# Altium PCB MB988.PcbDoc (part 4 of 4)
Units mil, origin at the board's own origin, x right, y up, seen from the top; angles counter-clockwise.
Board outline 4505 x 6805 mil, 4 copper layers (TopLayer, VCC, GND, BottomLayer), stack 71.6 mil thick; 546 components, 390 nets, 1907 pads, 809 vias.
Unrouted connection lines stored in the file: 2.
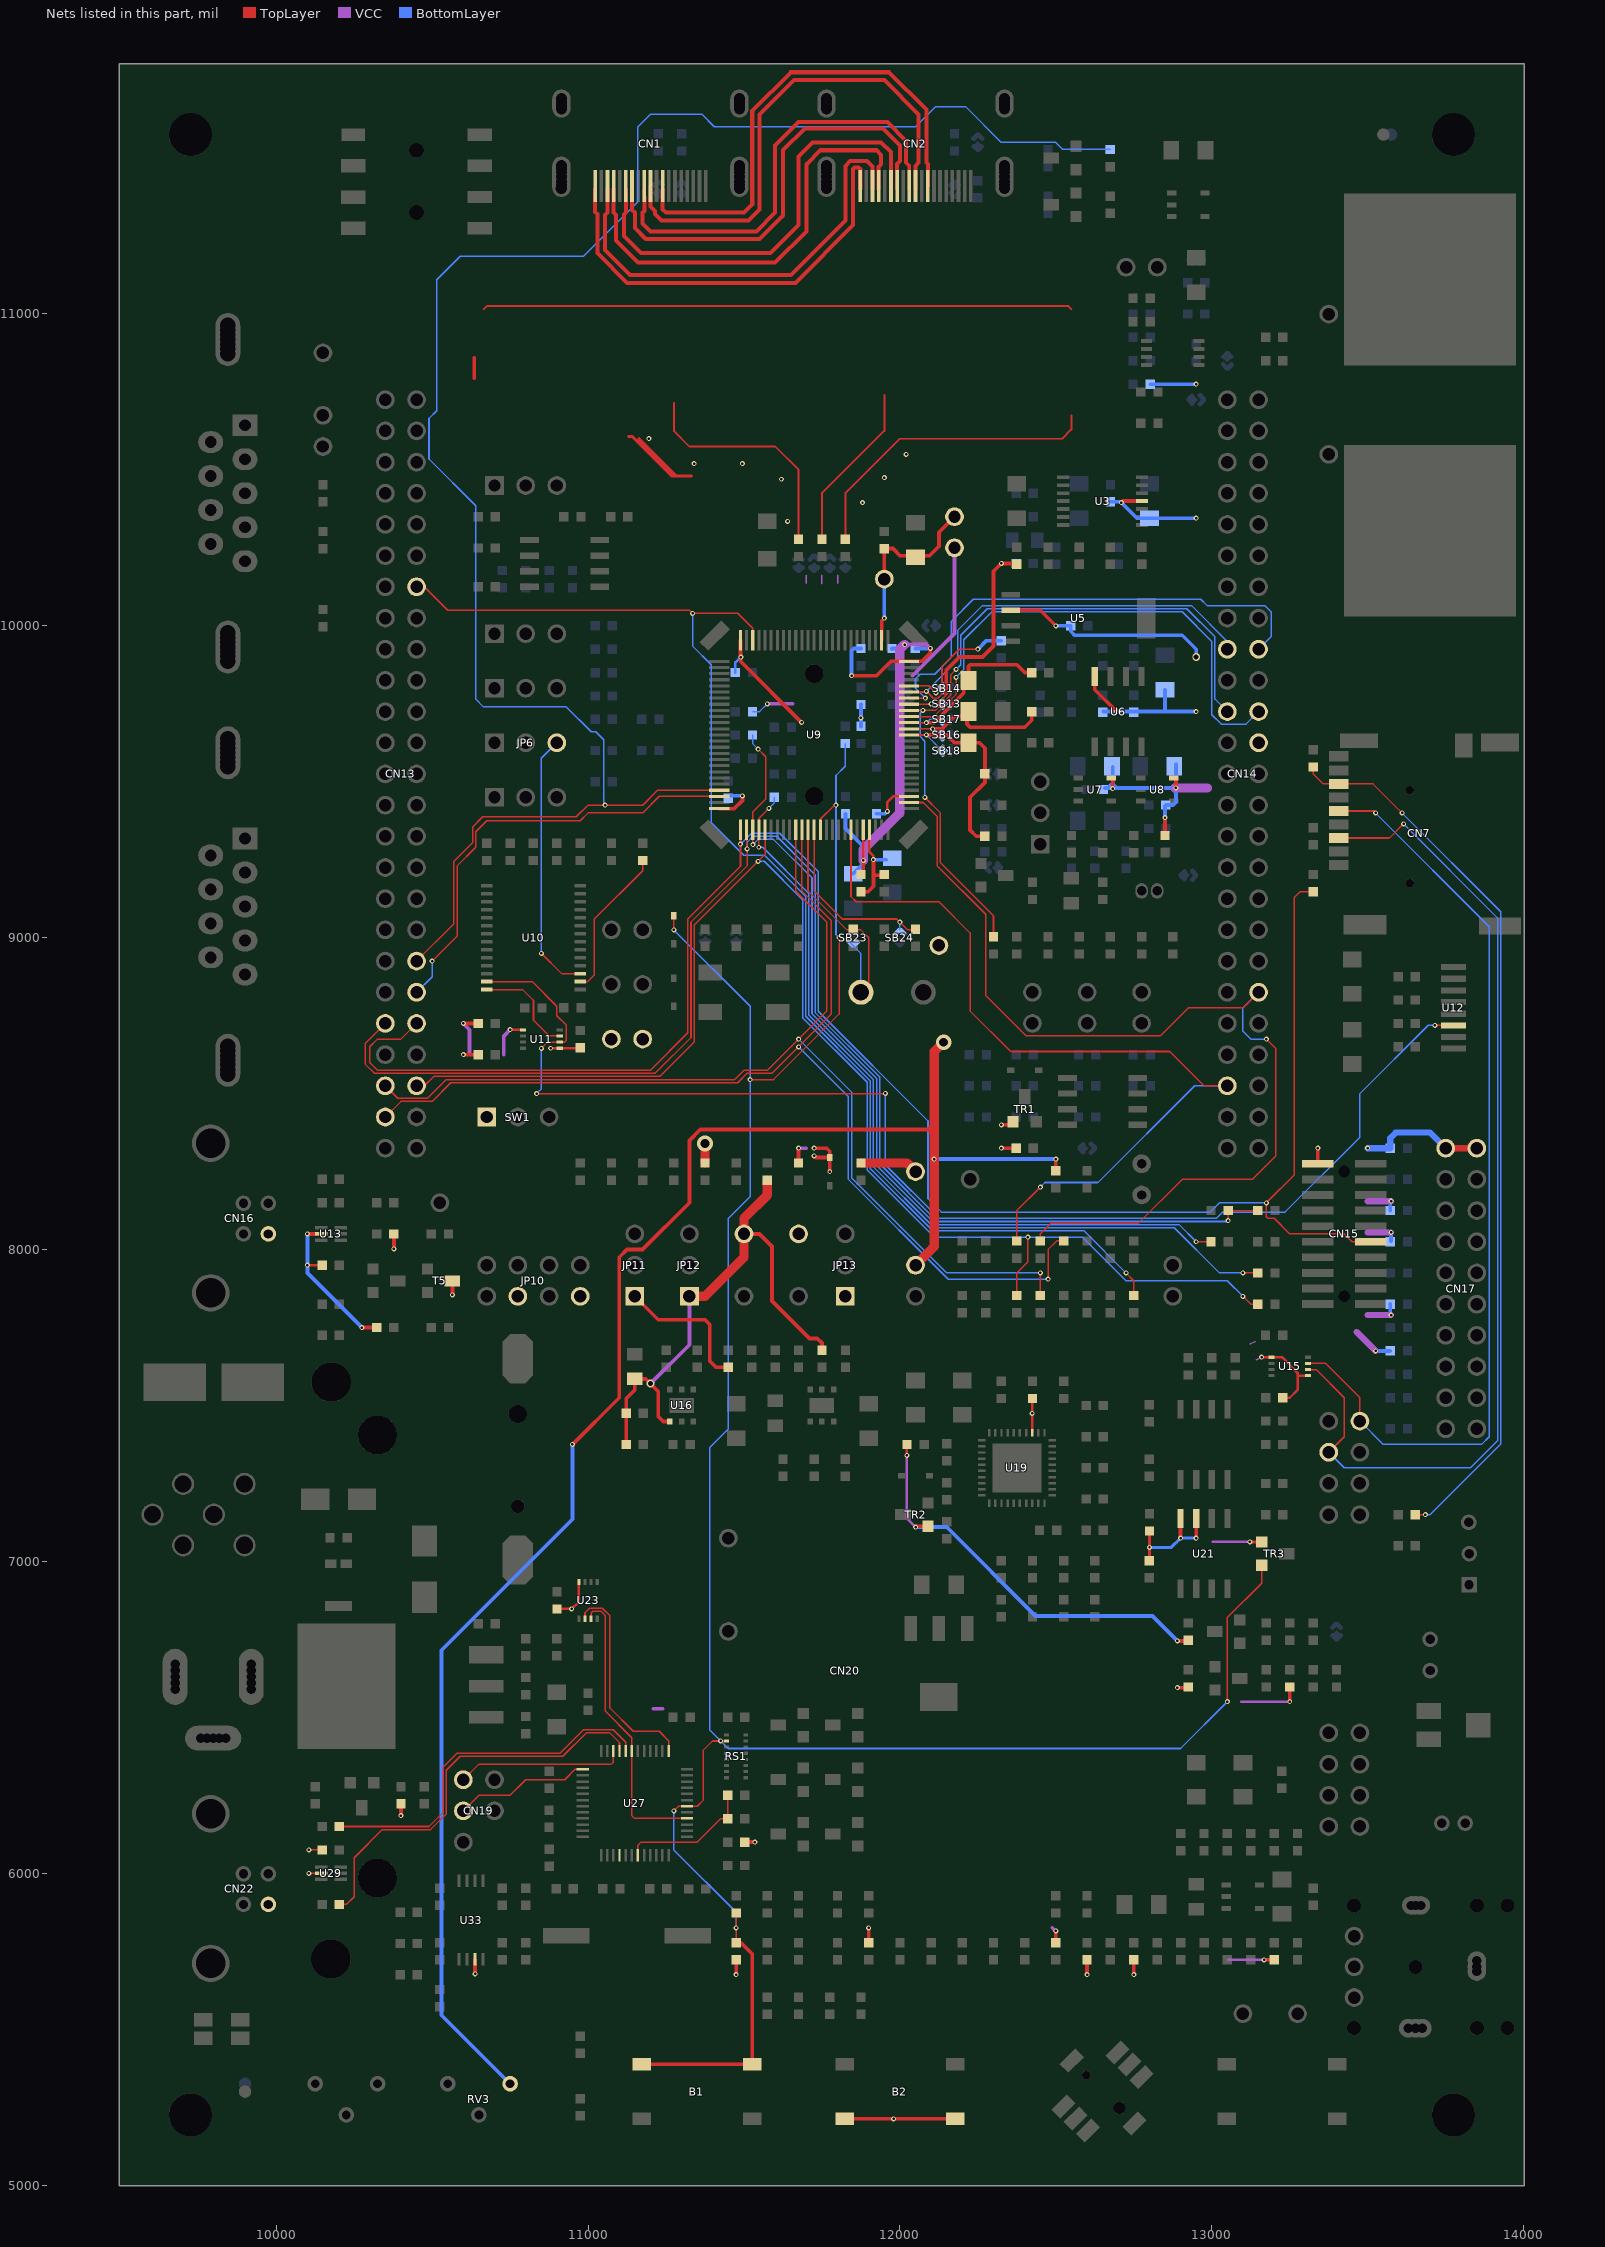
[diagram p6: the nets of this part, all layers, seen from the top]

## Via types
v1: diameter 16, hole 8, TopLayer to BottomLayer, tented both sides, 786 vias
v2: diameter 25, hole 16, TopLayer to BottomLayer, tented both sides, 20 vias
v3: diameter 50, hole 28, TopLayer to BottomLayer, tented both sides, 3 vias

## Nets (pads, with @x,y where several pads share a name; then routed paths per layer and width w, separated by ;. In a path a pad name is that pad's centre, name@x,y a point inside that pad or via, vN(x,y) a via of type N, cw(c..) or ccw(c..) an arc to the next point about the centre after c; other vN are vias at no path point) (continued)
PE0: CN13.38 R176.1 U9.97 | length 6058.2
  TopLayer w5: CN13.38@10450,8925 10570,9045 10570,9245 10630,9305 10630,9355 10662.5,9387.5 10962.5,9387.5 11000,9425 11175,9425 11222.83,9472.83 U9.97@11420.87,9472.83
  BottomLayer w5: v1(11055,9425) 11050,9430 11050,9635 11025,9660 11010,9660 10930,9740 10665,9740 10640,9765 10640,10385 10490,10535 10490,10665 10515,10690 10515,11110 10590,11185 10985,11185 11160,11360 11160,11600 11200,11640 11365,11640 11405,11600 12050,11600 12115,11665 12210,11665 12325,11550 12500,11550 12522.5,11527.5 R176.1@12675,11527.5
PE1: CN13.40 U9.98 | length 1421.4
  TopLayer w5: v1(10500,8925) 10580,9005 10580,9230 10640,9290 10640,9340 10675,9375 10975,9375 11000,9400 11175,9400 11228.15,9453.15 U9.98@11420.87,9453.15
  BottomLayer w5: CN13.40@10450,8825 10500,8875 v1(10500,8925)
PE2: CN13.42 CN15.12 R35.2 U9.1 | length 6154.1
  TopLayer w5: CN13.42@10450,8725 10400,8675 10325,8675 10300,8650 10300,8600 10325,8575 11200,8575 11320,8695 11320,9060 11488.78,9228.78 U9.1@11488.78,9345.87 ; R35.2@13325,9147.5 13282.5,9147.5 13265,9130 13265,8240 v1(13175,8150) 13175,8105 13180,8100 13200,8100 13250,8050 13425,8050 13450,8025 CN15.12@13510,8025
  BottomLayer w5: v1(11488.78,9300) 11523.78,9335 11615,9335 11738,9212 11738,8764.28 12090,8412.28 12090,8163.28 12133.28,8120 12995,8120 13025,8150 v1(13175,8150)
PE3: CN13.41 R60.2 R64.2 U9.2 | length 4638.8
  TopLayer w5: CN13.41@10350,8725 10285,8660 10285,8595 10315,8565 11215,8565 11330,8680 11330,9050 11510,9230 v1(11510,9285) 11508.46,9283.46 U9.2@11508.46,9345.87 ; v1(13052.5,8092.5) R60.2@13052.5,8125 R64.2@13147.5,8125
  BottomLayer w5: v1(11510,9285) 11510,9305 11530,9325 11605,9325 11728,9202 11728,8760.14 11935,8553.14 11935,8275 12120,8090 13050,8090 v1(13052.5,8092.5)
PE4: R29.2 R72.2 U9.3 | length 2816.3
  TopLayer w5: v1(11528.15,9298.15) 11528.15,9403.15 11570,9445 11570,9580 v1(11545,9605) ; v1(12950,8025) R72.2@12997.5,8025
  BottomLayer w5: R29.2@11527.5,9650 11527.5,9622.5 v1(11545,9605) ; v1(11528.15,9298.15) 11545,9315 11595,9315 11718,9192 11718,8756 11925,8549 11925,8270 12115,8080 12895,8080 v1(12950,8025)
PE5: R73.2 R83.2 U9.4 | length 2738.1
  TopLayer w5: v1(11547.83,9290) 11547.83,9382.83 v1(11580,9415) ; v1(13100,7925) R83.2@13147.5,7925
  BottomLayer w5: v1(11547.83,9290) 11560,9290 11708,9142 11708,8751.85 11915,8544.85 11915,8265 12110,8070 12880,8070 13025,7925 v1(13100,7925) ; v1(11580,9415) 11597.5,9432.5 R73.2@11597.5,9450
PE6: CN13.46 R85.2 R89.2 U9.5 | length 4502.4
  TopLayer w5: CN13.46@10450,8525 10475,8525 10505,8555 11230,8555 11340,8665 11340,9040 11567.52,9267.52 U9.5@11567.52,9345.87 ; R89.2@12375,7852.5 12375,7925 12410,7960 v1(12410,8040) ; v1(13100,7850) 13125,7825 R85.2@13147.5,7825
  BottomLayer w5: v1(11545,9245) 11565,9245 11688,9122 11688,8743.57 11895,8536.57 11895,8255 12110,8040 12585,8040 12725,7900 13050,7900 v1(13100,7850)
PE7: C11.1 C17.2 R34.1 SB18.2 U9.38 | length 665.4
  TopLayer w5: U9.38@12029.13,9650 v1(12085,9650)
  TopLayer w12: v1(12085,9650) 12150,9650 12175,9625 12255,9625 12272.5,9607.5 12272.5,9497.5 12225,9450 12225,9345 12245,9325 R34.1@12272.5,9325
  BottomLayer w5: v1(12085,9650) SB18.2@12132,9603
PE8: C10.1 R23.1 SB16.1 U9.39 | length 519.2
  TopLayer w5: U9.39@12029.13,9669.68 v1(12105,9669.68)
  TopLayer w12: v1(12105,9669.68) 12134.68,9669.68 12175,9710 C10.1@12220,9710 ; C10.1@12215,9710 12215,9685 12225,9675 12400,9675 12422.5,9697.5 R23.1@12422.5,9725
  BottomLayer w5: v1(12105,9669.68) SB16.1@12132,9642.68
PE9: C9.1 R21.1 SB17.1 U9.40 | length 570.1
  TopLayer w5: U9.40@12029.13,9689.37 v1(12085,9689.37)
  TopLayer w12: v1(12085,9689.37) 12109.37,9689.37 12205,9785 C9.1@12205,9825 ; C9.1@12220,9825 12220,9870 12225,9875 12375,9875 12400,9850 R21.1@12422.5,9850
  BottomLayer w5: v1(12085,9689.37) 12095.63,9700 12124,9700 SB17.1@12132,9708
PE10: CN14.22 U9.41 | length 1651.2
  TopLayer w5: U9.41@12029.13,9709.06 12109.06,9709.06 12180,9780 v1(12180,9835)
  BottomLayer w5: v1(12180,9835) 12205,9860 12205,9955 12295,10045 12905,10045 13000,9950 13000,9715 13030,9685 13110,9685 CN14.22@13150,9725
PE11: CN14.21 R39.1 U9.42 | length 2330.8
  TopLayer w5: U9.42@12029.13,9728.74 12113.74,9728.74 12162.4,9777.4 12162.4,9842.4 v1(12180,9860) ; v1(12080,9450) 12130,9400 12130,9240 12300,9070 R39.1@12300,9002.5
  BottomLayer w5: v1(12073.74,9728.74) 12065,9720 12065,9645 12080,9630 v1(12080,9450) ; v1(12180,9860) 12195,9875 12195,9970 12280,10055 12920,10055 13010,9965 13010,9765 CN14.21@13050,9725
PE12: R14.1 R183.1 SB13.2 U9.43 | length 797.8
  TopLayer w5: U9.43@12029.13,9748.42 v1@12100,9748.42 ; v1(12100,9750) 12120,9750 12145,9775 12145,9782.59 ; R14.1@12372.5,10197.5 R14.1@12375,10197.5
  TopLayer w12: 12148.5,9782.59 12148.5,9858.5 12190,9900 12265,9900 12300,9935 12300,10175 v1(12325,10200) R14.1@12372.5,10200
  BottomLayer w5: v1(12100,9750) SB13.2@12132,9750 ; v1(12325,10200) R183.1@12372.5,10200
PE13: CN14.18 U9.44 | length 1593.8
  TopLayer w5: U9.44@12029.13,9768.11 v1@12081.2,9768.11
  BottomLayer w5: v1(12081.55,9768.45) 12050,9800 12050,9830 12065,9845 12111.72,9845 12165,9898.28 12165,10015 12235,10085 12965,10085 12985,10065 13170,10065 13190,10045 13190,9965 CN14.18@13150,9925
PE14: CN14.17 R196.1 U9.45 | length 1641.5
  TopLayer w5: U9.45@12029.13,9787.8 12082.8,9787.8 v1(12085,9790) 12107.24,9767.76 12121.22,9767.76 12135,9781.54 12135,9870 12190,9925 v1(12250,9925)
  BottomLayer w5: v1(12085,9790) 12185,9890 12185,9985 12265,10065 12935,10065 13050,9950 CN14.17@13050,9925
  BottomLayer w12: v1(12250,9925) 12277.5,9952.5 R196.1@12325,9952.5
PE15: SB14.2 U9.46 | length 116.4
  TopLayer w5: U9.46@12029.13,9807.48 12092.52,9807.48 v1(12115,9785)
  BottomLayer w5: v1(12115,9785) SB14.2@12130,9800
PF0: C18.1 SB23.1 U9.12 X2.2 | length 808.9
  TopLayer w5: U9.12@11705.31,9345.87 11705.31,9149.69 11830,9025 11875,9025 11900,9000 11900,8850 X2.2@11875,8825
  BottomLayer w5: SB23.1@11842,8982 11875,8949 X2.2@11875,8825
PF1: R38.1 SB24.1 U9.13 | length 595.1
  TopLayer w5: U9.13@11725,9345.87 11725,9150 11815,9060 11990,9060 12025,9025 R38.1@12047.5,9025
  BottomLayer w5: SB24.1@12000,9025 v1(12000,9050)
PF2: CN14.45 R67.2 U9.19 | length 2756.9
  TopLayer w5: U9.19@11843.11,9345.87 11843.11,9131.89 11860,9115 12125,9115 12225,9015 12225,8765 12355,8635 12865,8635 12975,8525 CN14.45@13050,8525 ; R67.2@12375,8027.5 12375,8125 v1(12450,8200)
  BottomLayer w5: v1(12450,8200) 12465,8215 12635,8215 12945,8525 CN14.45@13050,8525
PF4: CN14.40 R68.2 U9.27 | length 3233.6
  TopLayer w5: U9.27@12029.13,9433.47 12075,9433.47 12120,9388.47 12120,9230 12275,9075 12275,8815 12405,8685 12835,8685 12925,8775 13100,8775 CN14.40@13150,8825 ; R68.2@12450,8027.5 12450,8050 12485,8085 12765,8085 12905,8225 13130,8225 13205,8300 13205,8645 v1(13175,8675)
  BottomLayer w5: CN14.40@13150,8825 13100,8775 13100,8700 13125,8675 v1(13175,8675)
PF6: CN13.14 R96.2 U9.73 | length 4267.3
  TopLayer w5: CN13.14@10450,10125 10475,10125 10550,10050 11325,10050 v1(11335,10040) 11480,10040 11528.15,9991.85 U9.73@11528.15,9954.13 ; v1(12725,7925) 12750,7900 R96.2@12750,7852.5
  BottomLayer w5: v1(11335,10040) 11335,9935 11395,9875 11395,9369.14 11499.57,9264.57 11565.43,9264.57 11698,9132 11698,8747.71 11905,8540.71 11905,8260 12105,8060 12590,8060 v1(12725,7925)
PF9: CN13.45 R91.2 U9.10 | length 3488.7
  TopLayer w5: CN13.45@10350,8525 10390,8485 10485,8485 10545,8545 11470,8545 11500,8575 11575,8575 11765,8765 11765,9050 11665.94,9149.06 U9.10@11665.94,9345.87 ; R91.2@12450,7852.5 v1(12450,7925)
  BottomLayer w5: v1(11675,8675) 11845,8505 11845,8230 12150,7925 v1(12450,7925)
PF10: CN13.47 R69.2 U9.11 | length 3616.9
  TopLayer w5: CN13.47@10350,8425 10400,8475 10500,8475 10560,8535 11480,8535 11510,8565 11590,8565 11780,8755 11780,9055 11685.63,9149.37 U9.11@11685.63,9345.87 ; v1(12475,7905) 12475,8000 12502.5,8027.5 R69.2@12525,8027.5
  BottomLayer w5: v1(11675,8650) 11835,8490 11835,8225 12155,7905 v1(12475,7905)
RESET#: B1.2 B1.3 C77.2 D1.1 R155.1 R203.2 RS1.3 TR3.1 U9.14 U27.18 | length 8053.2
  TopLayer w5: v1(11275,6200) 11290.16,6215.16 11350.16,6215.16 11370,6235 11370,6395 11399.21,6424.21 RS1.3@11444,6424.21 ; v1(11275,9025) D1.1@11275,9070 ; R155.1@11474.72,5777.78 C77.2@11474.72,5872.56 ; v1(11520,8545) 11595,8545 11805,8755 v1(11805,9000) ; U9.14@11744.68,9330 11744.68,9379.68 11790,9425 v1(11795,9425) ; v1(13050,6550) 13050,6820 13160,6930 TR3.1@13160,6987.5
  TopLayer w12: B1.2@11171.83,5387.5 B1.3@11526.17,5387.5 11526.17,5741.33 11490,5777.5 R155.1@11475,5777.5
  BottomLayer w5: v1(11275,6200) 11275,6075 11475,5875 v1(11475,5825) ; v1(11275,9025) 11520,8780 11520,8170 11450,8100 11450,7425 11390,7365 11390,6459.21 11449.21,6400 12900,6400 v1(13050,6550) ; v1(11795,9425) 11795.06,9425.06 11795.06,9520.06 11825,9550 R203.2@11825,9622.5 ; v1@11795.06,9425 11795.06,9009.94 v1(11805,9000)
  other v1: 11425,6424.21
SAR_VREF+: C20.2 C116.1 JP17.2 R32.2 TP5.1 U9.22 | length 772.2
  TopLayer w8: U9.22@11902.16,9345.87 11902.16,9275 11915,9262.16 v1(11915,9250)
  TopLayer w12: R32.2@11875,9147.5 11897.5,9147.5 11915,9165 v1(11915,9250) ; 11915,9200 C20.2@11947.85,9200
  VCC w12: 12040,9840 12175,9975 JP17.2@12175,10250
  BottomLayer w12: v1(11915,9250) C116.1@11955,9250
SD_VREF+: C4.2 C8.1 JP17.1 TP4.1 U9.52 | length 609.8
  TopLayer w12: U9.52@11941.53,9954.13 11941.53,10016.53 v1(11950,10025) ; TP4.1@11950,10150 11949.72,10150.28 C4.2@11949.72,10247.56 11977.44,10247.56 12000,10225 12095,10225 12125,10255 12125,10300 JP17.1@12175,10350
  BottomLayer w12: v1(11950,10025) TP4.1@11950,10150
SLD_1: R13.2 | length 2962.7
  TopLayer w6: 10665,11015 10675,11025 12540,11025 12550,11015 ; R13.2@11825,10277.5 11825,10425 12000,10600 12520,10600 12550,10630 12550,10675
  TopLayer w10: 10635,10793 10635,10860
SLD_2: R12.2 | length 545.3
  TopLayer w6: R12.2@11750,10277.5 11750,10425 11950,10625 11950,10740
SLD_3: R11.2 | length 764.3
  TopLayer w6: 11275,10715 11275,10625 11325,10575 11600,10575 11675,10500 R11.2@11675,10277.5
SPI3_MISO_3V3: CN7.7 R24.2 R247.2 | length 2881.7
  TopLayer w5: R24.2@13325,9547.5 13325,9525 13357.09,9492.91 13517.09,9492.91 v1(13610,9400) ; R247.2@13652.5,7150 v1(13685,7150)
  BottomLayer w5: v1(13610,9400) 13926.5,9083.5 13926.5,7376.5 13700,7150 v1(13685,7150)
SPI3_MOSI_3V3: CN7.3 CN20.3 U15.6 | length 3277.5
  TopLayer w5: U15.6@13309.06,7615.16 13334.84,7615.16 13425,7525 13425,7400 CN20.3@13375,7350 ; CN7.3@13406.65,9319.69 13569.69,9319.69 v1(13615,9365)
  BottomLayer w5: CN20.3@13375,7350 13425,7300 13830,7300 13916.5,7386.5 13916.5,9063.5 v1(13615,9365)
SPI3_SCK_3V3: CN7.5 CN20.2 U15.7 | length 3015
  TopLayer w5: U15.7@13309.06,7634.84 13365.16,7634.84 13475,7525 CN20.2@13475,7450 ; CN7.5@13406.65,9406.3 13518.7,9406.3 v1(13525,9400)
  BottomLayer w5: CN20.2@13475,7450 13550,7375 13865,7375 13890,7400 13890,9035 v1(13525,9400)
STL_USB_DM: R130.1 U27.32 | length 1175.6
  TopLayer w5: R130.1@10202.5,6150 10490,6150 10535,6195 10535,6340 10580,6385 10910,6385 10985,6460 11080.47,6460 11120.47,6420 U27.32@11120.47,6392.32
STL_USB_DP: R142.1 U27.33 | length 1321
  TopLayer w5: R142.1@10202.5,5900 10225,5900 10250,5925 10250,6050 10340,6140 10495,6140 10545,6190 10545,6330 10590,6375 10919.14,6375 10994.14,6450 11070,6450 11100.79,6419.21 U27.33@11100.79,6392.32
STM_JTCK_SWCLK: CN19.3 U27.37 | length 437.9
  TopLayer w5: CN19.3@10600,6200 10650,6250 10750,6250 10800,6300 10925,6300 10958.27,6333.27 U27.37@10982.68,6333.27
STM_JTMS_SWDIO: CN19.1 U27.34 | length 540.6
  TopLayer w5: CN19.1@10600,6300 10650,6350 11075,6350 11081.1,6356.1 U27.34@11081.1,6392.32
STM_RST: C63.2 R133.1 U27.7 | length 430.3
  TopLayer w5: U27.7@11159.84,6057.68 11159.84,6089.84 11170,6100 11350,6100 11425,6175 R133.1@11447.5,6175 ; R133.1@11447.56,6175.06 C63.2@11447.56,6250.28
SWIM_PU_CTRL: U27.4
T_SWDIO_IN: U23.2 U27.25 | length 675.5
  TopLayer w5: U23.2@10990.16,6815.94 10990.16,6835.16 11005,6850 11045.86,6850 11070,6825.86 11070,6530 11145,6455 11228.27,6455 11258.27,6425 U27.25@11258.27,6392.32
T_SWO: U23.3 U27.16 U27.31 | length 929.8
  TopLayer w5: U23.3@11009.84,6815.94 11009.84,6834.84 11015,6840 11041.72,6840 11055,6826.72 11055,6520 11140.16,6434.84 11140.16,6184.84 11149.21,6175.79 U27.16@11317.32,6175.79
"TMDS CLOCK+": CN1.10 CN2.10 | length 1604.3
  TopLayer w13: CN1.10@11200,11410 11200,11345 11214.74,11330.26 11214.74,11320.26 11235,11300 11515,11300 11550,11335 11550,11640 11660,11750 11950,11750 12060,11640 12060,11485 12050,11475 CN2.10@12050,11400
"TMDS CLOCK-": CN1.12 CN2.12 | length 1573.1
  TopLayer w13: CN1.12@11239.37,11400 11239.37,11335.63 11250,11325 11500,11325 11526.46,11351.46 11526.46,11651.46 11650,11775 11965,11775 12085,11655 12085,11485 12089.37,11480.63 CN2.12@12089.37,11410
"TMDS DATA0+": CN1.7 CN2.7 | length 1429.8
  TopLayer w13: CN1.7@11140.94,11400 11140.94,11334.06 11150,11325 11150,11275 11185,11240 11550,11240 11625,11315 11625,11525 11695,11595 11945,11595 12000,11540 12000,11490 11990.94,11480.94 CN2.7@11990.94,11400
"TMDS DATA0-": CN1.9 CN2.9 | length 1422.6
  TopLayer w12: CN1.9@11180.31,11375 CN1.9@11180.31,11400 ; 12020,11485 12030.31,11474.69 CN2.9@12030.31,11400
  TopLayer w13: CN1.9@11180.31,11375 11180.31,11330.31 11175,11325 11175,11290 11200,11265 11540,11265 11600,11325 11600,11540 11675,11615 11960,11615 12020,11555 12020,11485
"TMDS DATA1+": CN1.4 CN2.4 | length 1441.7
  TopLayer w13: CN1.4@11081.89,11400 11081.89,11325 11090,11316.89 11090,11235 11160,11165 11600,11165 11700,11265 11700,11480 11745,11525 11924.54,11525 11940,11509.54 11940,11480 11931.89,11471.89 CN2.4@11931.89,11400
"TMDS DATA1-": CN1.6 CN2.6 | length 1419.2
  TopLayer w13: CN1.6@11121.26,11400 11121.26,11325 11115,11318.74 11115,11250 11170,11195 11585,11195 11675,11285 11675,11505 11720,11550 11940,11550 11971.26,11518.74 CN2.6@11971.26,11420
"TMDS DATA2+": CN1.1 CN2.1 | length 1415.9
  TopLayer w13: CN1.1@11022.83,11400 11022.83,11327.17 11030,11320 11030,11195 11125,11100 11665,11100 11850,11285 11850,11465 11855,11470 11867.83,11470 11872.83,11465 CN2.1@11872.83,11400
"TMDS DATA2-": CN1.3 CN2.3 | length 1421.9
  TopLayer w12: CN2.3@11912.2,11400 CN2.3@11912.2,11420
  TopLayer w13: CN1.3@11062.2,11400 11062.2,11325 11055,11317.8 11055,11205 11135,11125 11650,11125 11825,11300 11825,11475 11840,11490 11895,11490 11912.2,11472.8 CN2.3@11912.2,11420
TS_SHIELD: R31.2 | length 641
  TopLayer w10: 11130,10607.06 11141.94,10607.06 11269,10480 11332,10480 ; 11163,10600 11283,10480
  VCC w5: 11700,10137.39 11700,10162.61 ; 11750,10135.4 11750,10162.61 ; 11800,10137.39 11800,10162.61
  VCC w12: v1(11575,9750) 11655.62,9750 11656,9750.38
  BottomLayer w5: R31.2@11527.5,9725 11550,9725 v1(11575,9750)
  other v1: 11640,10335 11880,10395 11620,10470 11950,10475 11340,10520 11495,10520 12020,10550 11195,10600
U5V: C122.1 CN16.1 JP10.3 R86.1 U13.5 | length 532.5
  TopLayer w8: v1(10100,7950) 10100.28,7949.72 C122.1@10147.44,7949.72
  TopLayer w12: v1(10100,8050) U13.5@10143.7,8050 ; v1(10275,7750) R86.1@10322.5,7750
  VCC w12: JP10.3@10775,7850 JP10.3@10790,7835
  BottomLayer w12: v1(10100,8050) 10100,7925 v1(10275,7750)
U5V_ST_LINK: C134.1 CN22.1 JP10.7 R131.1 U29.5 | length 121.2
  TopLayer w5: v1(10105,6000) U29.5@10143.7,6000 ; v1(10105,6075) C134.1@10150,6075
  TopLayer w12: v1(10400,6185) R131.1@10400,6222.5
USART2_CTS: R210.2 U10.16 | length 485.7
  TopLayer w5: U10.16@10974.61,8859.25 10999.25,8859.25 11020,8880 11020,9060 11175,9215 R210.2@11175,9247.5
USART2_RTS: U10.14 U11.7 | length 332.6
  TopLayer w5: U10.14@10675.39,8833.66 10790,8833.66 10825,8798.66 10825,8735 10875.16,8684.84 U11.7@10909.06,8684.84
USART2_RXD: JP6.3 U10.17 | length 847.3
  TopLayer w5: v1(10850,8950) 10915.16,8884.84 U10.17@10974.61,8884.84
  BottomLayer w5: v1(10850,8950) 10850,9575 JP6.3@10900,9625
USART2_TXD: U10.13 U11.6 U12.3 | length 4199.1
  TopLayer w5: U10.13@10675.39,8859.25 10820.75,8859.25 10900,8780 10900,8750 10930,8720 10930,8670 10925.16,8665.16 10870.16,8665.16 v1(10850,8645) ; v1(10835,8500) v1@11952.01,8500 ; v1(13715,8718.9) U12.3@13775,8718.9
  BottomLayer w5: v1(10835,8500) 10850,8515 v1(10850,8645) ; v1(11953.16,8501.15) 11953.16,8271.84 12125,8100 13015,8100 13035,8120 13235,8120 13475,8360 13475,8500 13693.9,8718.9 v1(13715,8718.9)
VDD: B2.1 B2.4 C44.1 C119.2 C125.2 C129.1 C131.1 CN14.24 CN15.1 CN17.1 CN17.2 JP11.1 JP15.2 R46.2 R47.2 R50.2 R55.1 R65.2 R102.1 R108.2 R117.1 R122.2 R124.1 R134.1 R155.2 R158.1 R162.1 R167.2 R169.1 R224.2 R225.2 R227.2 R228.2 R231.2 R236.1 R245.2 SW1.1 T5.3 TP10.1 TR1.2 TR2.2 TR3.2 U11.1 U11.5 U15.1 U15.5 U19.33 U21.7 U21.8 U23.8 U33.3 | length 5577.8
  TopLayer w8: v1@10750.47,8704.53 U11.1@10790.94,8704.53 ; v1(10880,8645.47) C119.2@10972.63,8645.47 ; C131.1@10900.28,6847.44 v1(10947.44,6847.44) 10970.47,6870.47 U23.8@10970.47,6934.06 ; v1(12022.5,7340) R108.2@12022.5,7375 ; U19.33@12424.21,7412.99 C44.1@12424.21,7521.37 ; v1(13160,7655) 13224.53,7655 13275,7604.53 13275,7549.72 13250,7524.72 C125.2@13227.56,7524.72 ; 13275,7595 13308.58,7595 U15.5@13309.06,7595.47
  TopLayer w10: JP11.1@11150,7850 11225,7775 ; R236.1@12800.28,7002.78 C129.1@12800.28,7097.44 ; v1(13122.5,7062.5) TR3.2@13160,7062.5
  TopLayer w12: v1(10377.5,8002.5) R65.2@10377.5,8050 ; v1(10565,7855) T5.3@10565,7899.5 ; v1(10600,8625) R47.2@10647.5,8625 ; v1(10600,8725) R46.2@10647.5,8725 ; v1(10637.8,5677.2) U33.3@10637.8,5724.02 ; 11225,7775 11375,7775 11390,7760 11390,7642.5 11410,7622.5 R102.1@11450,7622.5 ; v1(11475,5675) R155.2@11475,5722.5 ; R134.1@11502.5,6100 v1(11535,6100) ; B2.1@11822.83,5212.5 B2.4@12177.17,5212.5 ; R158.1@11900,5777.5 v1(11900,5825) ; v1(12050,7110) 12052.5,7112.5 TR2.2@12090,7112.5 ; v1(12325,8325) R50.2@12372.5,8325 ; v1(12325,8400) TR1.2@12355,8400 ; R162.1@12500,5777.5 v1(12500,5815) ; v1(12600,5675) R167.2@12600,5722.5 ; v1(12750,5675) R169.1@12750,5722.5 ; v1(12890,6595) R122.2@12925,6595 ; v1(12890,6745) R117.1@12925,6745 ; v1(12900,7075) U21.8@12900,7137.5 ; v1(12950,7075) U21.7@12950,7137.5 ; v1(13167.5,5722.5) R245.2@13200,5722.5 ; v1(13250,6550) R124.1@13250,6597.5 ; CN15.1@13340,8275 v1(13340,8325)
  TopLayer w20: CN17.1@13750,8325 CN17.2@13850,8325
  TopLayer w30: R55.1@11375,8277.5 v3(11375,8340)
  VCC w5: 13122.87,7697.15 13138.52,7704 ; 13142.87,7647.15 v1(13160,7655)
  VCC w8: v1(12022.5,7340) 12022.5,7137.5 v1(12050,7110) ; 13002.5,7062.5 v1(13122.5,7062.5) ; 13052.5,5722.5 v1(13167.5,5722.5) ; 13095,6550 v1(13250,6550)
  VCC w10: 11209,6527.5 11240,6527.5
  VCC w12: v1(10600,8725) 10620,8705 10620,8630 ; 10730,8625 10730,8685 v1(10750,8705) ; 12488.34,5825 v1@12499.17,5814.17
  VCC w20: 13464,7736 v1(13525,7675) ; 13500,7790 v1(13575,7790) ; 13500,8055 v1(13575,8055) ; 13500,8155 v1(13575,8155)
  BottomLayer w10: v1(12800.28,7045) 12870,7045 v1(12900,7075) v1(12950,7075)
  BottomLayer w12: v1(12050,7110) 12150,7110 12435,6825 12810,6825 v1(12890,6745) ; v1@12947.5,7072.5 v1(12950,7075) ; v1(13525,7675) R231.2@13572.5,7675 ; R228.2@13572.5,7825 13572.5,7792.5 v1(13575,7790) ; R225.2@13572.5,8125 13572.5,8152.5 v1(13575,8155) ; R227.2@13575,8027.5 v1(13575,8055)
  BottomLayer w20: v1(13500,8325) R224.2@13572.5,8325 13572.5,8357.5 13590,8375 13700,8375 CN17.1@13750,8325
  other v1: 11980,5212.5 12424.21,7475
VDD_ADJ: C31.1 C35.2 JP12.1 R57.2 R100.2 R106.1 TP9.1 U16.4 | length 1814.4
  TopLayer w12: C35.2@11122.5,7375 11122.5,7522.5 11150,7550 C31.1@11150,7585 11185,7585 11225,7545 11225,7465 11241.18,7448.82 U16.4@11262.6,7448.82 ; TP9.1@11520,8050 TP9.1@11500,8050 11550,8050 11590,8010 11590,7835 11710,7715 11735,7715 11750,7700 R100.2@11750,7677.5
  TopLayer w30: JP12.1@11325,7850 11375,7850 11500,7975 TP9.1@11500,8050 11500,8100 11575,8175 R57.2@11575,8222.5
  VCC w12: v2(11200,7570) 11325,7695 JP12.1@11325,7850
VDD_ANA: C93.2 C95.1 C100.2 C105.2 C106.1 C107.2 C108.1 C109.1 C111.2 JP16.1 R27.1 R59.2 R180.2 R205.1 RV3.1 U3.4 U5.3 U6.8 U7.5 U8.5 | length 8011.6
  TopLayer w12: v1(10950,7375) 11100,7525 11100,7975 11125,8000 11175,8000 11325,8150 11325,8350 11360,8385 12110,8385 ; 12110,8365 12090,8385 12110,8405 ; U5.3@12355,10050 12450,10050 v1(12500,10000) ; R59.2@12500,8252.5 v1(12500,8290) ; U6.8@12625,9837.5 12625,9795 v1(12695,9725) ; v1(12682.08,9477.92) U7.5@12682.08,9508.47 ; v1(12710,10395) 12715,10400 U3.4@12775.98,10400 ; R27.1@12850,9327.5 v1(12850,9385) ; v1(12885,9480) U8.5@12885,9515
  TopLayer w30: JP16.1@12050,7950 12110,8010 12110,8635 v3(12140,8665)
  VCC w30: v1(12885,9480) 12985,9480
  BottomLayer w12: RV3.1@10750,5325 10530,5545 10530,6715 10950,7135 v1(10950,7375) ; v1(12110,8290) v1(12500,8290) ; v1(12500,10000) 12547.28,10000 C100.2@12547.56,9999.72 12547.56,9982.44 12560,9970 12905,9970 12950,9925 v2(12950,9900) ; R205.1@12652.5,9725 v1(12950,9725) ; C107.2@12657.15,9480 v1(12885,9480) ; C107.2@12667.08,9480 12682.08,9495 ; C93.2@12675.87,10398.15 12706.85,10398.15 12760,10345 v1(12950,10345) ; v1@12682.08,9480 C108.1@12682.08,9547.92 ; 12682.08,9492.92 12695,9480 ; R180.2@12802.5,10775 v1@12949.9,10775 ; v1(12850,9385) 12850,9422.85 C111.2@12852.44,9425.28 12875.28,9425.28 12885,9435 C109.1@12885,9555 ; 12850,9725 C106.1@12850,9795 ; 12885,9465 12870,9480 12885,9495
  other v1: 12950,10775.1
VDDA: C102.2 C103.2 C110.2 C117.1 L1.2 R32.1 R70.1 TP6.1 U9.21 U9.50 | length 1902.4
  TopLayer w8: v1(11882.48,9247.52) U9.21@11882.48,9345.87
  TopLayer w12: v1(11845,9840) 11925,9840 11971.22,9886.22 12071.22,9886.22 12097.56,9912.56 v1(12097.56,9927.44) ; R32.1@11882.48,9202.52 v1(11882.48,9247.52)
  TopLayer w30: L1.2@11875,8277.5 12022.5,8277.5 TP6.1@12050,8250
  VCC w12: v1(12015,9940) 12085,9940 v1(12097.56,9927.44)
  VCC w30: v1(11882.48,9247.52) 11882.48,9282.48 11999,9399 11999,9924 v1(12015,9940)
  BottomLayer w12: C110.2@11825.28,9397.56 11825.28,9349.72 11882.48,9292.52 11882.48,9237.48 C117.1@11850,9205 ; v1(11845,9840) 11845,9920 11852.5,9927.5 R70.1@11875,9927.5 ; C102.2@11974.72,9924.72 C102.2@11977.44,9927.44 ; C102.2@11974.72,9927.44 12002.44,9927.44 v1(12015,9940) ; C103.2@12049.72,9927.44 v1(12097.56,9927.44)
VDDIO: C59.1 C99.1 C112.1 C115.1 D4.1 JP13.1 JP15.1 R58.1 R80.1 U9.28 U9.75 U9.100 | length 998.6
  TopLayer w8: v1(11960,9405) 11960,9435 11978.15,9453.15 U9.28@12029.13,9453.15
  TopLayer w12: U9.100@11420.87,9413.78 11468.78,9413.78 11495,9440 v1(11495,9455) ; U9.75@11488.78,9954.13 11488.78,9901.22 v1(11490,9900) 11490,9885 v1(11684.73,9690.27) ; R58.1@11675,8277.5 v1(11675,8325) ; v1(11725,8300) 11730,8295 D4.1@11775,8295 ; v1(11725,8325) 11765,8325 11775,8315 v1(11775,8250)
  VCC w12: v1(11675,8325) 11700,8325
  BottomLayer w8: C99.1@11472.44,9850.28 11472.44,9882.44 v1(11490,9900)
  BottomLayer w12: C112.1@11457.28,9455 v1(11495,9455) ; R80.1@11875,9747.5 v1(11875,9705) 11875,9677.85 C115.1@11875.28,9677.56 ; C59.1@11924.72,9397.44 11952.44,9397.44 v1(11960,9405)
pads on no net: BT1.0 CN1.14 CN2.14 CN3.0 CN5.1 CN5.4 CN5.8 CN7.1 CN7.8 CN7.H CN12.1 CN12.4 CN12.9 CN15.0 CN15.7 CN19.5 CN20.0 CN20.4 CN20.5 CN20.6 CN21.0 D6.1 D7.1 D8.1 D9.1 D10.1 D11.1 MP1.0 MP2.0 MP3.0 MP4.0 RS1.1 RS1.2 RS1.15 RS1.16 U1.3 U4.5 U5.5 U9.0 U10.4 U10.8 U10.11 U10.12 U10.15 U10.18 U10.19 U10.21 U12.2 U16.3 U18.1 U19.20 U19.21 U19.22 U19.23 U19.24 U19.25 U19.26 U19.36 U27.11 U27.12 U27.13 U27.14 U27.21 U27.22 U27.28 U27.38 U27.39 U27.40 U27.41 U27.42 U27.43 U27.45 U27.46 U33.7 U34.H X1.2 X1.3

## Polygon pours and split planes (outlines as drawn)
TS_SHIELD on TopLayer "TopLayer-TS_SHIELD" (hatched 90Degree grid 10 track 10, remove dead copper, pour order 16): 10600,11075 12650,11075 12650,10525 12050,10525 11880,10355 11880,10150 11828.42,10098.42 11828.42,10025 11725,10025 11725,10055 11625,10155 11625,10375 11525,10475 11300,10475 11175,10600 10585,10600 10585,11075
SLD_3 on TopLayer "TopLayer-SLD_3" (hatched 90Degree grid 5 track 5, remove dead copper, pour order 14): 10700,11014.02 11853.55,11014.02 11853.55,10640.29 10700,10640.29
SLD_2 on TopLayer "TopLayer-SLD_2" (hatched 90Degree grid 5 track 5, remove dead copper, pour order 12): 11350,11014.02 12507.09,11014.02 12507.09,10640.29 11360,10640.29 11360,11014.02
SLD_1 on TopLayer "TopLayer-SLD_1" (hatched 90Degree grid 5 track 5, remove dead copper, pour order 10): 12507.09,11014.02 12592.25,11014.02 12592.25,10640.29 12015,10640.29 12015,11014.02 12505,11014.02
SLD_1 on TopLayer "TopLayer-SLD_1 1" (hatched 90Degree grid 5 track 5, remove dead copper, pour order 8): 10622.5,11014.02 11196.07,11014.02 11196.07,10640.29 10622.79,10640.29 10622.79,11014.02
NetC29_2 on TopLayer "TopLayer-NetC29_2" (hatched 90Degree grid 25 track 15, remove dead copper, pour order 6): 9505,8400 10000,8400 10000,7925 10175,7925 10175,7700 9500,7700 9500,8400
AGND on TopLayer "TopLayer-AGND" (hatched 90Degree grid 25 track 15, remove dead copper, pour order 4): 12345,9075 13025,9075 13025,10775 13175,10775 13300,10650 13300,9875 14000,9875 14000,11800 13200,11800 13200,11240 12675,11240 12675,10490 12080,10490 11905,10315 11905,9880 12000,9880 12000,9630 12060,9630 12060,9520 12345,9520
GND on TopLayer "TopLayer-GND" (hatched 90Degree grid 25 track 15, remove dead copper, pour order 2): 10205,11810 13205,11810 13205,11285 12695,11285 12695,10520 12090,10520 11920,10350 11920,10052.69 12115,9857.69 12115,9600.94 12310,9600.94 12370.94,9540 12370.94,9080 13080,9080 13080,10760 13230,10760 13330,10660 13330,9860 14030,9860 14030,5010 9530,5010 9530,11085 10205,11085
AGND on VCC "VCC-AGND" (hatched 90Degree grid 8 track 10, remove dead copper, pour order 56): 12410,9065 12935,9065 12935,10785 12950,10800 13155,10800 13295,10660 13295,9910 14000,9910 14000,11800 13050,11800 13050,11255 13040,11245 12700,11245 12665,11210 12665,10495 12085,10495 11900,10310 11900,10075 11995,9980 12095,9980 12095,9635 12180,9550 12250,9550 12250,9485 12220,9455 12220,9320 12240,9300 12400,9300 12420,9280 12450,9250 12450,9100 12345,9100 12325,9080 12325,8870 12395,8800 12460,8800 12460,8855 12360,8955 12360,9060 12365,9065
VDD_ANA on VCC "VCC-VDD_ANA" (hatched 90Degree grid 8 track 10, remove dead copper, pour order 54): 12944,10783.1 13025,10783.1 13025,8672 12975,8622 12130,8622 12121,8631 12121,8695 12925,8695 12952,8722 12952,9890 12940,9902 12940,10783.1
VDD on VCC "VCC-VDD" (hatched 90Degree grid 8 track 10, remove dead copper, pour order 52): 11496,5581.05 10635,5581.05 10610,5606.05 10610,5670 10635,5695 10690,5695 10715,5670 11365,5670 11405,5710 11490,5625 11490,5584
VDDIO on VCC "VCC-VDDIO" (hatched 90Degree grid 8 track 10, remove dead copper, pour order 50): 11840,7795 11981.72,7795 12000,7813.28 12000,8175 11932,8243 11932,8915 11830,9017 11830,9264 11969,9403 11969,9965 11920,9965 11870,10015 11820,10015 11820,9860 11487.9,9527.9 11480,9520 11480,9300 11605,9300 11605,9180 11135,8710 11135,8585 11080,8530 11080,8460 11615,8460 11690,8385 11690,8173.28 11813.28,8050 11813.28,7800 11840,7800
VDDA on VCC "VCC-VDDA" (hatched 90Degree grid 8 track 10, remove dead copper, pour order 48): 12080,8610 12080,8312 12120,8272 12120,8215 12100,8195 12000,8195 11952,8243 11952,8920 11845,9027 11845,9256 11889,9300 11890,9300 11890,9065 12015,8940 12015,8785 12080,8720
SAR_VREF+ on VCC "VCC-SAR_VREF+" (hatched 90Degree grid 8 track 10, remove dead copper, pour order 46): 12080,8920 12150,8920 12170,8940 12170,9010 12075,9105 12075,9845 12185,9955 12185,10250 12160,10250 12160,9975 12025,9840 12025,9385 11915,9275 11915,9070 12065,8920
TS_SHIELD on VCC "VCC-TS_SHIELD" (hatched 90Degree grid 8 track 10, remove dead copper, pour order 44): 10585,11075 10585,10605 11135,10605 11280,10460 11530,10460 11575,10415 11575,10180 11660,10095 11660,9795 11635,9770 11565,9770 11565,9732.56 11685,9732.56 11807.44,9855 11807.44,10075 11875,10142.56 11875,10320 12065,10510 12645.35,10510 12645.35,11075
+3V3 on VCC "VCC-+3V3" (hatched 90Degree grid 8 track 10, remove dead copper, pour order 42): 10450,10575 10450,8405 10564.17,8405 10599.17,8440 10599.17,8665 11000,8665 11054.72,8719.72 11120,8719.72 11570,9169.72 11570,9275 11535,9310 11475,9310 11475,9510 11561.28,9596.28 11655,9690 11655,9710 11640,9725 11568,9725 11548,9745 11548,9768 11564,9784 11632,9784 11640,9792 11640,10080 11550,10170 11550,10390 11500,10440 11272,10440 11138,10574 10450,10574
+3V3 on VCC "VCC-+3V3 1" (hatched 90Degree grid 8 track 10, remove dead copper, pour order 40): 13215,9740 13775,9740 13825,9690 13825,6085 13720,5980 13720,5340 13505,5125 9785,5125 9650,5260 9650,7185 10155,7185 10058,7088 10058,5824.15 10095,5824.15 10140.85,5870 10140.85,6095 10185.85,6140 10390,6140 10390,6232.32 10160,6232.32 10160,6655 10635,6655 10715,6735 10929.19,6735 10929.19,6495 10990,6434.19 11180,6434.19 11200.65,6454.84 11360.59,6454.84 11395,6420.43 11395,6330 11485,6240 11485,6135 11385,6035 11385,5620 11445,5560 11860,5560 11935,5485 11935,5225 12790,5225 13080,5515 13125,5560 13125,5831.93 13016.93,5940 13016.93,6189.39 13190,6362.46 13190,6569 13120,6569 13075,6614 13075,7520 13205,7650 13445,7650 13525,7730 13525,8350 13465,8410 13285,8410 13230,8465 13210,8485 13210,9740
VDD on VCC "VCC-VDD 1" (hatched 90Degree grid 8 track 10, remove dead copper, pour order 38): 10370,8005 10520,7855 10525,7850 10565,7850 10575,7860 10590,7875 10590,8015 10610,8035 10925,8035 10925,7990 10940,7975 10995,7975 11105,7865 11120,7850 11120,7790 11235,7790 11280,7835 11315,7870 11705,7870 11705,7830.8 11735,7800.8 11735,7705 11795,7645 12013.23,7645 12130,7528.23 12310,7528.23 12348.23,7490 12402.8,7490 12402.8,7470 12412.8,7460 12430,7460 12430,7490 12402.8,7517.2 12402.8,7727.2 12335,7795 12335,8500 12380,8545 12690,8545 12690,8495.42 12600,8495.42 12570,8465.42 12570,7910 12640,7840 12950,7840 12991.67,7798.33 12991.67,7678.56 12946.67,7633.56 12946.67,7525 12865,7443.33 12865,7150 12635,6920 12635,6280 12540,6185 11915,6185 11835,6265 11835,6615 11760,6690 11370,6690 11370,6545 11082.5,6545 11082.5,7300 11020,7300 10710,6990 10710,6750 10940,6750 10940,6500 10990,6450 11380.36,6450 11425,6405.36 11425,6335 11500,6260 11500,6121.77 11396.05,6017.82 11396.05,5630 11445,5581.05 11890,5581.05 11950,5521.05 11950,5201.14 11999.31,5201.14 11999.31,5235 12790.86,5235 13110,5554.14 13110,5818.2 12998.2,5930 12998.2,6200 13175,6376.8 13175,6560 13055,6680 13055,7515 13215,7675 13435,7675 13520,7760 13520,8340 13470,8390 13295,8390 13200,8485 13200,9736 13045,9736 13045,8669.72 12975.28,8600 12025,8600 12025,7810 11990,7775 11820,7775 11820,8025 11680,8165 11680,8385 11615,8450 11045,8450 11045,8555 11105,8615 11105,8700 11040,8700 11015,8675 10599,8675 10599,8145 10534.64,8080.64 10428.64,8080.64 10370,8022
+5V on VCC "VCC-+5V" (hatched 90Degree grid 8 track 10, remove dead copper, pour order 36): 10600,7990 10600,7935 10640,7895 10980,7895 11065,7810 11065,7575 10535,7045 10215,7045 10164.88,6994.88 10164.88,6670 10625,6670 10700,6745 10700,6990 11022,7312 11360,7312 11367,7305 11367,6710 11760,6710 11850,6620 11850,6260 11905,6205 12545,6205 12615,6275 12615,6925 12845,7155 12845,7445 12928.13,7528.13 12928.13,7630 12985,7686.87 12985,7775 12940,7820 12630,7820 12560,7890 12550,7900 12550,8490 12575,8515 12695,8515 12695,8535 12390,8535 12350,8495 12350,7800 12415,7735 12415,7530 12450,7495 12450,7465 12430,7445 12430,7105 12405,7080 12340,7080 12195,6935 12195,6610 12170,6585 12090,6585 12070,6605 12065,6610 12065,6960 12262.38,7157.38 12320,7215 12320,7360 12270,7410 12100,7410 11970,7540 11770,7540 11745,7515 11745,7270 11710,7235 11655,7235 11630,7260 11630,7355 11565,7420 11565,7525 11435,7655 11435,7850 11120,7850 11090,7880 11065,7905 11065,7960 11005,8020 10620,8020 10600,8000
+5V on VCC "VCC-+5V 1" (hatched 90Degree grid 8 track 10, remove dead copper, pour order 34): 10575,8145 10575,8365 10550,8390 10425,8390 10405,8410 10405,8470 10385,8490 10310,8490 10310,10915 10495,11100 12530,11100 12685,11255 13000,11255 13015,11240 13015,11195 13020,11190 13035,11190 13040,11195 13040,11385 13030,11395 12825,11395 12735,11305 10945,11305 10870,11380 10870,11785 10180,11785 10180,11075 9510,11075 9510,8350 10370,8350 10395,8325 10395,8220 10450,8165 10450,8115 10465,8100 10525,8100 10565,8140
D5V on VCC "VCC-D5V" (hatched 90Degree grid 8 track 8, remove dead copper, pour order 32): 13025,9835 13025,9785 13055,9755 13775,9755 13835,9695 13835,6085 13730,5980 13730,5340 13505,5115 9770,5115 9635,5250 9635,8050 9775,8190 10090,8190 10150,8130 10150,7913.55 10288.55,7775 10690,7775 10690,7855 10530,7855 10409.64,7975.36 10409.64,8287.25 10371.89,8325 9527.5,8325 9527.5,5020 13990,5020 13990,9885 13060,9885 13025,9850
E5V on VCC "VCC-E5V" (hatched 90Degree grid 8 track 10, remove dead copper, pour order 30): 10875,7850 10835,7850 10820,7835 10820,7700 10650,7530 9810,7530 9655,7375 9655,7220 9670,7205 10500,7205 10920,7625 10920,7835 10905,7850
U5V_ST_LINK on VCC "VCC-U5V_ST_LINK" (hatched 90Degree grid 8 track 10, remove dead copper, pour order 28): 10975,7850 10950,7825 10950,7615 10500,7165 10175,7165 10055,7045 10055,6005 9970,5920 9970,5830 10000,5800 10060,5800 10140,5880 10140,6105 10185,6150 10390,6150 10410,6170 10410,6195 10390,6215 10180,6215 10140,6255 10140,6990 10210,7060 10530,7060 11050,7580 11050,7825 11030,7845 10975,7845
+1V8 on VCC "VCC-+1V8" (hatched 90Degree grid 8 track 10, remove dead copper, pour order 26): 11450,7785 11450,7660 11575,7535 11575,7420 11640,7355 11640,7270 11660,7250 11700,7250 11725,7275 11725,7480 11590,7615 11590,7830 11565,7855 11480,7855 11450,7825
+2V5 on VCC "VCC-+2V5" (hatched 90Degree grid 8 track 10, remove dead copper, pour order 24): 12085,6675 12085,6630 12110,6605 12170,6605 12185,6620 12185,6940 12335,7090 12400,7090 12415,7105 12415,7373 12360,7428 12360,7475 12325,7510 12120,7510 12000,7630 11800,7630 11726.5,7703.5 11726.5,7820 11686.5,7860 11670,7860 11630,7820 11630,7690 11765,7555 11975,7555 12105,7425 12275,7425 12340,7360 12340,7215 12085,6960
HDMI_5V_SINK on VCC "VCC-HDMI_5V_SINK" (hatched 90Degree grid 10 track 10, remove dead copper, pour order 22): 11125,11800 12100,11800 12100,11590 12133.84,11556.16 12305,11556.16 12373.84,11625 12800,11625 12800,11400 12725,11325 10950,11325 10950,11800
HDMI_5V_SOURCE on VCC "VCC-HDMI_5V_SOURCE" (hatched 90Degree grid 10 track 10, remove dead copper, pour order 20): 12100,11790 13175,11790 13175,11390 12825,11390 12825,11640 12355,11640 12285,11570 12160,11570 12140,11590 12125,11590 12125,11790
U5V on VCC "VCC-U5V" (hatched 90Degree grid 8 track 10, remove dead copper, pour order 18): 10710,7855 10810,7855 10810,7708.28 10650,7548.28 9810,7548.28 9711.72,7450 9635,7450 9635,8048 9767,8180 10100.96,8180 10150,8130.96 10150,7915 10264.98,7800.02 10685,7800.02 10695.02,7790 10695.02,7850
GND on BottomLayer "BottomLayer-GND" (hatched 90Degree grid 25 track 15, remove dead copper, pour order 58): 10175,11800 14000,11800 14000,5000 9500,5000 9500,11075 10175,11075
no net on TopOverlay (hatched 90Degree grid 5 track 5): 6860,10275 6860,10649.02 6785,10634 6785,10275
no net on TopOverlay (hatched 90Degree grid 5 track 5): 4965,10275 4965,10287 4900,10275 4965,10275
no net on TopOverlay (hatched 90Degree grid 5 track 5): 5065,10275 5065,10306 4985,10291 4985,10275 5065,10275
no net on TopOverlay (hatched 90Degree grid 5 track 5): 5165,10275 5165,10325 5085,10310 5085,10275
no net on TopOverlay (hatched 90Degree grid 5 track 5): 5265,10275 5265,10344 5185,10329 5185,10275 5264,10275
no net on TopOverlay (hatched 90Degree grid 5 track 5): 5360,10275 5360,10362 5285,10348 5285,10275 5359,10275
no net on TopOverlay (hatched 90Degree grid 5 track 5): 5380,10275 5380,10366 5465,10383 5465,10275
no net on TopOverlay (hatched 90Degree grid 5 track 5): 5565,10275 5565,10401 5485,10386 5485,10275
no net on TopOverlay (hatched 90Degree grid 5 track 5): 5665,10275 5665,10421 5585,10405 5585,10275
no net on TopOverlay (hatched 90Degree grid 5 track 5): 5765,10275 5765,10440 5685,10425 5685,10275 5763,10275
no net on TopOverlay (hatched 90Degree grid 5 track 5): 5860,10275 5860,10458 5785,10444 5785,10275 5859,10275
no net on TopOverlay (hatched 90Degree grid 5 track 5): 5880,10275 5880,10462 5965,10478 5965,10275
no net on TopOverlay (hatched 90Degree grid 5 track 5): 6065,10275 6065,10498 5985,10482 5985,10275 6064,10275
no net on TopOverlay (hatched 90Degree grid 5 track 5): 6165,10275 6165,10516 6085,10501 6085,10275
no net on TopOverlay (hatched 90Degree grid 5 track 5): 6265,10275 6265,10535 6185,10520 6185,10275
no net on TopOverlay (hatched 90Degree grid 5 track 5): 6360,10275 6360,10553 6285,10539 6285,10275
no net on TopOverlay (hatched 90Degree grid 5 track 5): 6380,10275 6380,10557 6465,10573 6465,10275
no net on TopOverlay (hatched 90Degree grid 5 track 5): 6685,10275 6685,10615 6765,10630 6765,10275
no net on TopOverlay (hatched 90Degree grid 5 track 5): 6585,10275 6585,10596 6665,10611 6665,10275
no net on TopOverlay (hatched 90Degree grid 5 track 5): 6485,10275 6485,10577 6565,10592 6565,10275
GND on GND (split plane): 13982.11,5017.89 9517.89,5017.89 9517.89,11100 10160,11100 10160,11782.11 13982.11,11782.11
GND on GND (split plane): 11220.67,7045.92 11220.67,6927.16 11102.16,6927.16 11102.16,7047.84 11221.46,7047.84
HDMI_5V_SOURCE on GND (split plane): 11341.59,6929.33 11229.33,6929.33 11229.33,7041.59 11341.59,7041.59

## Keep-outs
KeepOutLayer:
  circle w5: c10550,5325 r50
  lines w4: 11100,6550 11100,6675 ; 11100,6800 11225,6800 11350,6800 ; 11100,6925 11225,6925 11350,6925 ; 11100,7050 11225,7050 11350,7050 ; 11225,6550 11225,6675 ; 11225,7300 11225,7175 ; 11100,6675 11225,6675 ; 11100,6675 11100,7175 ; 11100,7175 11100,7300 11350,7300 11350,7175 ; 11100,7175 11225,7175 ; 11225,6675 11350,6675 11350,7175 ; 11225,6675 11225,7175 ; 11225,7175 11350,7175
  lines w5: 9500,6450 9500,8170 9500,11800 14000,11800 14000,9623.99 ccw(c15173.78,9374.49) 14000,9125 14000,5000 9500,5000 9500,6458.87 ; 11100,6550 11350,6550 11350,6675

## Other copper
TopLayer:
  text "1" at 11200,6725 h50 r90
  text "B" at 11310,6715 h50 r90
VCC:
  text "2" at 11200,6845 h50 r90
  text "B" at 11310,6845 h50 r90
BottomLayer:
  text "4" at 11200,7135 h50 r90
  text "B" at 11310,7135 h50 r90
GND (plane layer: these items are gaps in the copper):
  rectangle: 9500,11100 10160,11800
  region: 11100,6925 11100,7050 11075,7050 11075,6925
  region: 11375,6925 11375,7050 11350,7050 11350,6925
  region: 11375,7050 11375,7320 11075,7320 11075,7050
  rectangle: 11075,6525 11375,6925
  lines w4: 11100,6550 11100,6675 ; 11100,6800 11220,6800 ; 11100,6925 11225,6925 11350,6925 ; 11100,7050 11225,7050 11350,7050 ; 11220,6675 11225,6675 ; 11225,6550 11225,6675 ; 11225,6800 11350,6800 ; 11350,6550 11350,6675 ; 11100,6675 11225,6675 ; 11100,6675 11100,7175 11225,7175 ; 11225,6675 11225,7175 ; 11225,6675 11350,6675 ; 11225,7175 11350,7175 11350,6675
  lines w8: 11905,6460 11905,6470 ; 11225,6925 11225,7045.92 11345.92,7045.92 11345.92,6925 11225,6925
  text "3" at 11200,7010 h50 r90
  text "B" at 11310,7010 h50 r90

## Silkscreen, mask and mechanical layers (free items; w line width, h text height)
TopOverlay:
  drawing of 6264 lines, arcs and shapes, not listed
  text "E2PROM RF" at 10215,11660 h50
  text "1" at 10770,11655 h35
  text "HDMI_Sink" at 11075,11250 h50
  text "HDMI_Source" at 11925,11250 h50
  text "ECG_amp_ADJ" at 12565,11225 h35
  text "CAN" at 9780,11060 h50
  text "GND" at 10095,10935 h35
  text "1" at 13040,10800 h35
  text "1" at 10345,10795 h35
  text "2" at 10425,10795 h35
  text "2" at 13125,10795 h35
  text "GND" at 10200,10755 h35
  text "PC6" at 10510,10700 h35
  text "PD15" at 13210,10700 h35
  text "GND" at 12870,10685 h35
  text "PC7" at 10275,10600 h35 r90
  text "PC8" at 10510,10600 h35
  text "PD14" at 12875,10600 h35
  text "PD13" at 13210,10600 h35
  text "CAN_RS" at 10780,10520 h35
  text "CAN terminal" at 10075,10500 h35 r90
  text "PA8" at 10510,10500 h35
  text "PD11" at 12875,10500 h35
  text "PD12" at 13210,10500 h35
  text "PC9" at 10275,10475 h35 r90
  text "PA10" at 10180,10400 h35
  text "PA9" at 10510,10400 h35
  text "PD9" at 12875,10400 h35
  text "PD10" at 13210,10400 h35
  text "PA11" at 10180,10300 h35
  text "GND" at 10510,10300 h35
  text "GND" at 13215,10300 h35
  text "PC13" at 12875,10297.5 h35
  text "PC14" at 10175,10200 h35
  text "PA12" at 10510,10200 h35
  text "SD_VREF+" at 12285,10200 h35 r90
  text "RST" at 12895,10200 h35
  text "PD8" at 13210,10200 h35
  text "PA13" at 10175,10100 h35
  text "PF6" at 10510,10100 h35
  text "PB15" at 12870,10100 h35
  text "PB14" at 13210,10100 h35
  text "I2C2" at 10650,10040 h35
  text "I2C_F" at 10850,10040 h35
  text "SD_VREF+" at 11800,10035 h35
  text "PB10" at 12870,10005 h35
  text "PC15" at 10180,10000 h35
  text "PA14" at 10510,10000 h35
  text "PE15" at 13210,10000 h35
  text "PE14" at 12875,9905 h35
  text "PA15" at 10175,9900 h35
  text "PE13" at 13210,9900 h35
  text "PC10" at 10510,9885 h35
  text "I2C2" at 10650,9865 h35
  text "I2C_F" at 10850,9865 h35
  text "GND" at 10175,9800 h35
  text "PC11" at 10510,9800 h35
  text "D5V" at 12900,9800 h35
  text "PE12" at 13210,9800 h35
  text "USART" at 9715,9735 h50
  text "PD0" at 10175,9700 h35
  text "PE11" at 12885,9700 h35
  text "PE10" at 13210,9700 h35
  text "IRDA" at 10650,9690 h35
  text "RS232" at 10830,9690 h35
  text "PC12" at 10510,9680 h35
  text "uSD" at 13575,9675 h50
  text "PD2" at 10175,9600 h35
  text "PD1" at 10510,9600 h35
  text "PF0" at 12900,9600 h35
  text "VDD" at 13210,9600 h35
  text "RS232" at 10650,9510 h35
  text "BL_RST" at 10830,9510 h35
  text "PD4" at 10175,9500 h35
  text "PD3" at 10510,9500 h35
  text "PE9" at 12900,9500 h35
  text "PF1" at 13210,9500 h35
  text "REF" at 12395,9465 h35 r90
  text "PD6" at 10175,9400 h35
  text "PD5" at 10510,9400 h35
  text "PE8" at 12900,9400 h35
  text "PE7" at 13210,9400 h35
  text "PD7" at 10175,9300 h35
  text "GND" at 10510,9300 h35
  text "PB2" at 12900,9300 h35
  text "GND" at 13210,9300 h35
  text "PT100" at 12395,9250 h35 r90
  text "PT100_CN" at 12685,9210 h35
  text "PB3" at 10175,9200 h35
  text "PB4" at 10510,9200 h35
  text "PB0" at 13210,9200 h35
  text "PB1" at 12900,9160 h35
  text "PB5" at 10175,9100 h35
  text "PB6" at 10510,9100 h35
  text "PC5" at 12900,9100 h35
  text "PC4" at 13210,9100 h35
  text "BL_RST" at 11125,9090 h35
  text "Pin1" at 11410,9070 h30
  text "SAR_VREF+" at 12035,9070 h35
  text "PB7" at 10175,9000 h35
  text "PB8" at 10510,9000 h35
  text "PA7" at 12905,9000 h35
  text "PA6" at 13210,9000 h35
  text "BL_Boot0" at 11130,8920 h35
  text "PB9" at 10175,8900 h35
  text "PE0" at 10510,8900 h35
  text "PA5" at 12905,8900 h35
  text "PA4" at 13210,8900 h35
  text "SD" at 12365,8825 h35 r90
  text "GND" at 10175,8800 h35
  text "PE1" at 10510,8800 h35
  text "GND" at 12905,8800 h35
  text "PF4" at 13210,8800 h35
  text "SAR2" at 12540,8780 h35 r90
  text "SAR1" at 12710,8780 h35 r90
  text "VDDIO" at 11125,8735 h35
  text "PE3" at 10175,8700 h35
  text "PE2" at 10510,8700 h35
  text "PA3" at 12905,8700 h35
  text "PA2" at 13210,8700 h35
  text "IrDA" at 13975,8700 h50 r90
  text "PE5" at 10175,8600 h35
  text "PE4" at 10510,8600 h35
  text "PA1" at 12900,8600 h35
  text "PA0" at 13210,8600 h35
  text "Temp" at 12685,8595 h35
  text "JTAG" at 13800,8540 h50
  text "0<->1" at 10700,8510 h35
  text "PF9" at 10175,8500 h35
  text "PE6" at 10510,8500 h35
  text "PF2" at 12900,8500 h35
  text "PC3" at 13210,8500 h35
  text "PC1" at 13210,8405 h35
  text "PF10" at 10175,8400 h35
  text "3V3" at 10510,8400 h35
  text "PC2" at 12895,8400 h35
  text "USB" at 9880,8395 h50
  text "TRACE" at 13400,8345 h50
  text "LDR" at 12795,8330 h35
  text "GND" at 13210,8320 h35
  text "BOOT0" at 10760,8305 h35
  text "D5V" at 10175,8300 h35
  text "GND" at 10510,8300 h35
  text "PC0" at 12895,8300 h35
  text "0 = Flash" at 10640,8240 h35
  text "49" at 10325,8225 h35
  text "50" at 10425,8225 h35
  text "49" at 13025,8225 h35
  text "50" at 13125,8225 h35
  text "1 = Sys mem" at 10640,8165 h35
  text "3V3" at 12315,8160 h35
  text "5V" at 10415,8125 h35
  text "VDDA" at 11925,8125 h35
  text "VDD_ADJ" at 11395,8105 h35
  text "D5V" at 10700,8025 h50 r90
  text "U5V" at 10800,8025 h50 r90
  text "PSU" at 10900,8025 h50 r90
  text "STlk" at 11000,8025 h50 r90
  text "3V3" at 11765,8025 h35 r90
  text "VDD" at 11615,8005 h35 r90
  text "BAT" at 11080,8000 h35 r90
  text "3V3" at 11260,8000 h35 r90
  text "1V8" at 11425,7900 h35
  text "2V5" at 11575,7900 h35
  text "VDD" at 11765,7805 h35 r90
  text "VDD" at 11080,7800 h35 r90
  text "VDD_ANA" at 11980,7800 h35 r90
  text "E2P_WC" at 12815,7800 h35 r90
  text "power source" at 10635,7750 h50
  text "VDD_ADJ" at 11260,7735 h35 r90
  text "+" at 9520.91,6925 h50 r270
  text "-" at 9745.91,6890 h50
  text "DC5V" at 9850,6850 h40
  text "IR" at 13875,6800 h50
  text "B" at 11310,6600 h50 r90
  text "S" at 11200,6595 h50 r90
  text "PSU" at 9910,6375 h50
  text "Mic" at 13810,6325 h40
  text "ST-LINK/V2" at 9670,6270 h50
  text "Audio_out" at 13585,5970 h50
  text "COM" at 9575,5475 h40
  text "VDD>2.4V" at 11065,5385 h35 r90
  text "VDD<2.4V" at 11065,5105 h35 r90
BottomOverlay:
  drawing of 2834 lines, arcs and shapes, not listed
  text "B" at 11200,7250 h50 r90
  text "B" at 11310,7250 h50 r90
Mechanical1:
  lines w5: 9500,5000 14000,5000 14000,9125 cw(c15173.78,9374.49) 14000,9623.99 14000,11800 9500,11800 9500,8170 9500,6458.87 9500,5000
